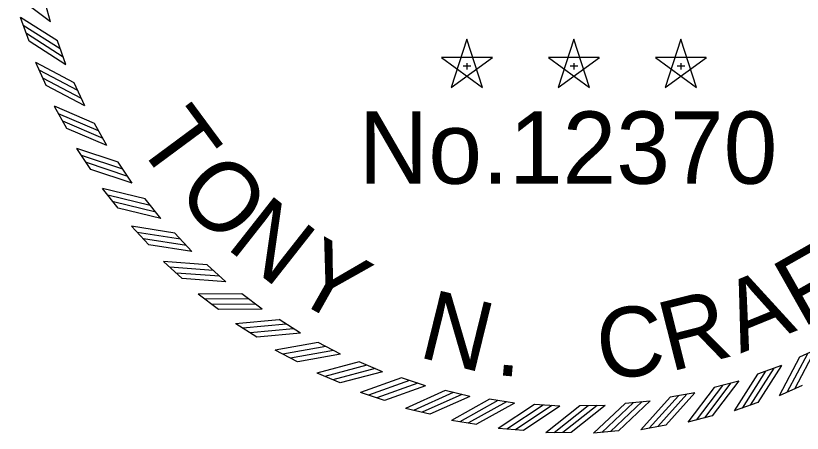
# Model space of a CAD drawing. Extents: x -712 to 3943, y 73 to 2823.
# Drawn here: x 3001.6 to 3144.5, y 203 to 278.8 of the extents above; entities that cross this region are included whole.
import ezdxf

# ---------------------------------------------------------------- set-up
doc = ezdxf.new("R2010")
doc.units = 0
doc.layers.add('STAMP_TNC', color=7, linetype='Continuous')

msp = doc.modelspace()

# ---------------------------------------------------------------- linework, layer by layer
at = {"layer": 'STAMP_TNC'}
for p, q in [((3007.88, 277.67), (3006.71, 282.11)), ((3007.88, 277.67), (3006.71, 282.11)), ((3004, 274.19), (3002.47, 278.51)), ((3004, 274.19), (3002.47, 278.51)), ((3083.56, 274.56), (3080.7, 265.76)), ((3083.56, 274.56), (3080.7, 265.76)), ((3086.42, 265.77), (3083.57, 274.57)), ((3086.42, 265.77), (3083.57, 274.57)), ((3103, 274.56), (3100.13, 265.76)), ((3103, 274.56), (3100.13, 265.76)), ((3105.86, 265.77), (3103.01, 274.57)), ((3105.86, 265.77), (3103.01, 274.57)), ((3122.43, 274.56), (3119.57, 265.76)), ((3122.43, 274.56), (3119.57, 265.76)), ((3125.29, 265.77), (3122.44, 274.57)), ((3125.29, 265.77), (3122.44, 274.57)), ((3010.68, 269.92), (3009.15, 274.25)), ((3010.68, 269.92), (3009.15, 274.25)), ((3007.1, 266.12), (3005.22, 270.3)), ((3007.1, 266.12), (3005.22, 270.3)), ((3088.19, 271.2), (3078.94, 271.21)), ((3088.19, 271.2), (3078.94, 271.21)), ((3078.94, 271.2), (3086.42, 265.75)), ((3078.94, 271.2), (3086.42, 265.75)), ((3080.71, 265.77), (3088.2, 271.2)), ((3080.71, 265.77), (3088.2, 271.2)), ((3083.57, 270.21), (3083.57, 269.05)), ((3083.57, 270.21), (3083.57, 269.05)), ((3107.62, 271.2), (3098.37, 271.21)), ((3107.62, 271.2), (3098.37, 271.21)), ((3098.38, 271.2), (3105.86, 265.75)), ((3098.38, 271.2), (3105.86, 265.75)), ((3100.14, 265.77), (3107.63, 271.2)), ((3100.14, 265.77), (3107.63, 271.2)), ((3103.01, 270.21), (3103.01, 269.05)), ((3103.01, 270.21), (3103.01, 269.05)), ((3127.06, 271.2), (3117.81, 271.21)), ((3127.06, 271.2), (3117.81, 271.21)), ((3117.81, 271.2), (3125.29, 265.75)), ((3117.81, 271.2), (3125.29, 265.75)), ((3119.58, 265.77), (3127.07, 271.2)), ((3119.58, 265.77), (3127.07, 271.2)), ((3122.44, 270.21), (3122.44, 269.05)), ((3122.44, 270.21), (3122.44, 269.05)), ((3082.91, 269.72), (3084.28, 269.72)), ((3082.91, 269.72), (3084.28, 269.72)), ((3102.34, 269.72), (3103.72, 269.72)), ((3102.34, 269.72), (3103.72, 269.72)), ((3121.78, 269.72), (3123.15, 269.72)), ((3121.78, 269.72), (3123.15, 269.72)), ((3014.11, 262.42), (3012.22, 266.61)), ((3014.11, 262.42), (3012.22, 266.61)), ((3010.85, 258.34), (3008.63, 262.35)), ((3010.85, 258.34), (3008.63, 262.35)), ((3018.14, 255.23), (3015.92, 259.25)), ((3018.14, 255.23), (3015.92, 259.25)), ((3015.23, 250.9), (3012.69, 254.71)), ((3015.23, 250.9), (3012.69, 254.71)), ((3022.76, 248.4), (3020.21, 252.23)), ((3022.76, 248.4), (3020.21, 252.23)), ((3020.21, 243.85), (3017.37, 247.44)), ((3020.21, 243.85), (3017.37, 247.44)), ((3027.92, 241.98), (3025.07, 245.58)), ((3027.92, 241.98), (3025.07, 245.58)), ((3025.76, 237.23), (3022.63, 240.57)), ((3025.76, 237.23), (3022.63, 240.57)), ((3033.6, 236), (3030.46, 239.35)), ((3033.6, 236), (3030.46, 239.35)), ((3031.84, 231.09), (3028.44, 234.16)), ((3031.84, 231.09), (3028.44, 234.16)), ((3039.75, 230.51), (3036.34, 233.59)), ((3039.75, 230.51), (3036.34, 233.59)), ((3038.4, 225.47), (3034.76, 228.25)), ((3038.4, 225.47), (3034.76, 228.25)), ((3046.33, 225.55), (3042.68, 228.34)), ((3046.33, 225.55), (3042.68, 228.34)), ((3053.3, 221.15), (3049.43, 223.63)), ((3053.3, 221.15), (3049.43, 223.63)), ((3045.41, 220.42), (3041.55, 222.89)), ((3045.41, 220.42), (3041.55, 222.89)), ((3060.61, 217.34), (3056.55, 219.49)), ((3060.61, 217.34), (3056.55, 219.49)), ((3148.2, 218.71), (3144.01, 216.83)), ((3148.2, 218.71), (3144.01, 216.83)), ((3052.8, 215.96), (3048.75, 218.1)), ((3052.8, 215.96), (3048.75, 218.1)), ((3068.21, 214.15), (3063.99, 215.96)), ((3068.21, 214.15), (3063.99, 215.96)), ((3140.7, 215.28), (3136.38, 213.75)), ((3140.7, 215.28), (3136.38, 213.75)), ((3060.54, 212.13), (3056.33, 213.93)), ((3060.54, 212.13), (3056.33, 213.93)), ((3076.05, 211.6), (3071.69, 213.05)), ((3076.05, 211.6), (3071.69, 213.05)), ((3132.95, 212.48), (3128.51, 211.32)), ((3132.95, 212.48), (3128.51, 211.32)), ((3144.5, 211.7), (3140.32, 209.82)), ((3144.5, 211.7), (3140.32, 209.82)), ((3068.57, 208.95), (3064.23, 210.39)), ((3068.57, 208.95), (3064.23, 210.39)), ((3084.07, 209.7), (3079.6, 210.78)), ((3084.07, 209.7), (3079.6, 210.78)), ((3124.99, 210.34), (3120.47, 209.54)), ((3124.99, 210.34), (3120.47, 209.54)), ((3092.22, 208.47), (3087.68, 209.18)), ((3092.22, 208.47), (3087.68, 209.18)), ((3116.89, 208.85), (3112.31, 208.43)), ((3116.89, 208.85), (3112.31, 208.43)), ((3076.84, 206.44), (3072.39, 207.52)), ((3076.84, 206.44), (3072.39, 207.52)), ((3100.44, 207.92), (3095.86, 208.25)), ((3100.44, 207.92), (3095.86, 208.25)), ((3108.68, 208.04), (3104.09, 208)), ((3108.68, 208.04), (3104.09, 208)), ((3136.44, 208.6), (3132.12, 207.07)), ((3136.44, 208.6), (3132.12, 207.07)), ((3128.14, 206.18), (3123.71, 205.01)), ((3128.14, 206.18), (3123.71, 205.01)), ((3085.28, 204.62), (3080.76, 205.34)), ((3085.28, 204.62), (3080.76, 205.34)), ((3119.68, 204.45), (3115.17, 203.65)), ((3119.68, 204.45), (3115.17, 203.65)), ((3093.85, 203.51), (3089.28, 203.85)), ((3093.85, 203.51), (3089.28, 203.85)), ((3102.48, 203.11), (3097.89, 203.07)), ((3102.48, 203.11), (3097.89, 203.07)), ((3111.11, 203.42), (3106.54, 203)), ((3111.11, 203.42), (3106.54, 203))]:
    msp.add_line(p, q, dxfattribs=at)
for points in [[(3007.89, 277.67), (3001.58, 282.47)], [(3007.89, 277.67), (3001.58, 282.47)], [(3009.15, 274.24), (3002.46, 278.51)], [(3009.15, 274.24), (3002.46, 278.51)], [(3009.64, 272.8), (3002.96, 277.06)], [(3009.64, 272.8), (3002.96, 277.06)], [(3010.2, 271.31), (3003.52, 275.58)], [(3010.2, 271.31), (3003.52, 275.58)], [(3010.68, 269.91), (3004, 274.18)], [(3010.68, 269.91), (3004, 274.18)], [(3012.22, 266.6), (3005.21, 270.3)], [(3012.22, 266.6), (3005.21, 270.3)], [(3012.84, 265.2), (3005.82, 268.91)], [(3012.84, 265.2), (3005.82, 268.91)], [(3013.52, 263.77), (3006.51, 267.47)], [(3013.52, 263.77), (3006.51, 267.47)], [(3014.11, 262.42), (3007.1, 266.12)], [(3014.11, 262.42), (3007.1, 266.12)], [(3015.92, 259.25), (3008.63, 262.36)], [(3015.92, 259.25), (3008.63, 262.36)], [(3016.65, 257.9), (3009.35, 261.01)], [(3016.65, 257.9), (3009.35, 261.01)], [(3017.45, 256.53), (3010.15, 259.64)], [(3017.45, 256.53), (3010.15, 259.64)], [(3018.15, 255.23), (3010.86, 258.34)], [(3018.15, 255.23), (3010.86, 258.34)], [(3020.21, 252.22), (3012.69, 254.72)], [(3020.21, 252.22), (3012.69, 254.72)], [(3021.05, 250.94), (3013.52, 253.44)], [(3021.05, 250.94), (3013.52, 253.44)], [(3021.96, 249.64), (3014.43, 252.13)], [(3021.96, 249.64), (3014.43, 252.13)], [(3022.76, 248.4), (3015.24, 250.9)], [(3022.76, 248.4), (3015.24, 250.9)], [(3025.07, 245.57), (3017.36, 247.44)], [(3025.07, 245.57), (3017.36, 247.44)], [(3026, 244.37), (3018.3, 246.23)], [(3026, 244.37), (3018.3, 246.23)], [(3027.02, 243.14), (3019.32, 245.01)], [(3027.02, 243.14), (3019.32, 245.01)], [(3027.93, 241.98), (3020.22, 243.85)], [(3027.93, 241.98), (3020.22, 243.85)], [(3030.46, 239.35), (3022.62, 240.57)], [(3030.46, 239.35), (3022.62, 240.57)], [(3031.49, 238.22), (3023.66, 239.45)], [(3031.49, 238.22), (3023.66, 239.45)], [(3032.61, 237.09), (3024.77, 238.31)], [(3032.61, 237.09), (3024.77, 238.31)], [(3033.6, 236), (3025.77, 237.23)], [(3033.6, 236), (3025.77, 237.23)], [(3036.34, 233.59), (3028.43, 234.16)], [(3036.34, 233.59), (3028.43, 234.16)], [(3037.47, 232.55), (3029.56, 233.13)], [(3037.47, 232.55), (3029.56, 233.13)], [(3038.67, 231.51), (3030.76, 232.09)], [(3038.67, 231.51), (3030.76, 232.09)], [(3039.75, 230.51), (3031.85, 231.09)], [(3039.75, 230.51), (3031.85, 231.09)], [(3042.68, 228.34), (3034.75, 228.25)], [(3042.68, 228.34), (3034.75, 228.25)], [(3043.89, 227.4), (3035.96, 227.32)], [(3043.89, 227.4), (3035.96, 227.32)], [(3045.17, 226.46), (3037.25, 226.38)], [(3045.17, 226.46), (3037.25, 226.38)], [(3046.34, 225.55), (3038.41, 225.47)], [(3046.34, 225.55), (3038.41, 225.47)], [(3049.44, 223.62), (3041.54, 222.89)], [(3049.44, 223.62), (3041.54, 222.89)], [(3050.71, 222.79), (3042.82, 222.05)], [(3050.71, 222.79), (3042.82, 222.05)], [(3052.07, 221.96), (3044.18, 221.23)], [(3052.07, 221.96), (3044.18, 221.23)], [(3053.31, 221.15), (3045.41, 220.42)], [(3053.31, 221.15), (3045.41, 220.42)], [(3056.55, 219.49), (3048.75, 218.1)], [(3056.55, 219.49), (3048.75, 218.1)], [(3057.9, 218.76), (3050.09, 217.38)], [(3057.9, 218.76), (3050.09, 217.38)], [(3059.32, 218.05), (3051.51, 216.66)], [(3059.32, 218.05), (3051.51, 216.66)], [(3060.62, 217.35), (3052.81, 215.96)], [(3060.62, 217.35), (3052.81, 215.96)], [(3145.42, 217.44), (3141.71, 210.43)], [(3145.42, 217.44), (3141.71, 210.43)], [(3146.85, 218.12), (3143.15, 211.11)], [(3146.85, 218.12), (3143.15, 211.11)], [(3063.99, 215.95), (3056.32, 213.93)], [(3063.99, 215.95), (3056.32, 213.93)], [(3144.02, 216.83), (3140.32, 209.82)], [(3144.02, 216.83), (3140.32, 209.82)], [(3065.39, 215.34), (3057.72, 213.31)], [(3065.39, 215.34), (3057.72, 213.31)], [(3066.87, 214.75), (3059.2, 212.72)], [(3066.87, 214.75), (3059.2, 212.72)], [(3139.31, 214.81), (3135.05, 208.13)], [(3139.31, 214.81), (3135.05, 208.13)], [(3140.71, 215.29), (3136.44, 208.61)], [(3140.71, 215.29), (3136.44, 208.61)], [(3068.22, 214.15), (3060.55, 212.13)], [(3068.22, 214.15), (3060.55, 212.13)], [(3071.69, 213.04), (3064.22, 210.39)], [(3071.69, 213.04), (3064.22, 210.39)], [(3136.38, 213.75), (3132.11, 207.07)], [(3136.38, 213.75), (3132.11, 207.07)], [(3137.82, 214.25), (3133.56, 207.56)], [(3137.82, 214.25), (3133.56, 207.56)], [(3073.14, 212.55), (3065.66, 209.9)], [(3073.14, 212.55), (3065.66, 209.9)], [(3074.66, 212.08), (3067.19, 209.43)], [(3074.66, 212.08), (3067.19, 209.43)], [(3076.05, 211.6), (3068.58, 208.95)], [(3076.05, 211.6), (3068.58, 208.95)], [(3130, 211.69), (3125.19, 205.38)], [(3130, 211.69), (3125.19, 205.38)], [(3131.53, 212.13), (3126.72, 205.82)], [(3131.53, 212.13), (3126.72, 205.82)], [(3132.96, 212.49), (3128.15, 206.18)], [(3132.96, 212.49), (3128.15, 206.18)], [(3079.61, 210.78), (3072.38, 207.52)], [(3079.61, 210.78), (3072.38, 207.52)], [(3081.09, 210.41), (3073.86, 207.15)], [(3081.09, 210.41), (3073.86, 207.15)], [(3123.54, 210.1), (3118.23, 204.21)], [(3123.54, 210.1), (3118.23, 204.21)], [(3125, 210.34), (3119.69, 204.45)], [(3125, 210.34), (3119.69, 204.45)], [(3128.52, 211.31), (3123.71, 205.01)], [(3128.52, 211.31), (3123.71, 205.01)], [(3082.64, 210.06), (3075.42, 206.8)], [(3082.64, 210.06), (3075.42, 206.8)], [(3084.07, 209.7), (3076.85, 206.44)], [(3084.07, 209.7), (3076.85, 206.44)], [(3087.69, 209.18), (3080.75, 205.33)], [(3087.69, 209.18), (3080.75, 205.33)], [(3089.19, 208.93), (3082.26, 205.08)], [(3089.19, 208.93), (3082.26, 205.08)], [(3090.77, 208.71), (3083.83, 204.87)], [(3090.77, 208.71), (3083.83, 204.87)], [(3115.42, 208.74), (3109.64, 203.31)], [(3115.42, 208.74), (3109.64, 203.31)], [(3116.89, 208.86), (3111.11, 203.43)], [(3116.89, 208.86), (3111.11, 203.43)], [(3120.48, 209.54), (3115.17, 203.65)], [(3120.48, 209.54), (3115.17, 203.65)], [(3121.98, 209.79), (3116.67, 203.9)], [(3121.98, 209.79), (3116.67, 203.9)], [(3092.22, 208.47), (3085.29, 204.63)], [(3092.22, 208.47), (3085.29, 204.63)], [(3095.87, 208.25), (3089.27, 203.85)], [(3095.87, 208.25), (3089.27, 203.85)], [(3097.39, 208.12), (3090.79, 203.72)], [(3097.39, 208.12), (3090.79, 203.72)], [(3098.98, 208.04), (3092.38, 203.64)], [(3098.98, 208.04), (3092.38, 203.64)], [(3100.45, 207.92), (3093.85, 203.52)], [(3100.45, 207.92), (3093.85, 203.52)], [(3104.1, 208), (3097.89, 203.07)], [(3104.1, 208), (3097.89, 203.07)], [(3105.62, 208), (3099.42, 203.07)], [(3105.62, 208), (3099.42, 203.07)], [(3107.21, 208.05), (3101.01, 203.12)], [(3107.21, 208.05), (3101.01, 203.12)], [(3108.69, 208.05), (3102.48, 203.12)], [(3108.69, 208.05), (3102.48, 203.12)], [(3112.32, 208.43), (3106.54, 203)], [(3112.32, 208.43), (3106.54, 203)], [(3113.84, 208.56), (3108.06, 203.13)], [(3113.84, 208.56), (3108.06, 203.13)]]:
    msp.add_lwpolyline(points, dxfattribs=at)

# ---------------------------------------------------------------- texts
for s, rotation, p in [('T', 306.5026, (3023.13, 256)), ('T', 306.5026, (3023.13, 256)), ('O', 313.7811, (3030.31, 246.29)), ('O', 313.7811, (3030.31, 246.29)), ('N', 321.7876, (3039.56, 236.77)), ('N', 321.7876, (3039.56, 236.77)), ('Y', 330.5218, (3051.05, 227.95)), ('Y', 330.5218, (3051.05, 227.95)), ('F', 29.4782, (3144.47, 222.02)), ('F', 29.4782, (3144.47, 222.02)), ('A', 22.1996, (3133.29, 217.46)), ('A', 22.1996, (3133.29, 217.46)), ('N', 346.1707, (3074.47, 216.89)), ('N', 346.1707, (3074.47, 216.89)), ('R', 14.1932, (3120.44, 214.12)), ('R', 14.1932, (3120.44, 214.12)), ('C', 6.5507, (3107.85, 212.63)), ('C', 6.5507, (3107.85, 212.63)), ('.', 354.905, (3088.57, 213.61)), ('.', 354.905, (3088.57, 213.61))]:
    msp.add_text(s, height=12.66, rotation=rotation, dxfattribs=at).set_placement(p)
msp.add_text('No.12370', height=13.119, dxfattribs=at).set_placement((3063.89, 248.3))
msp.add_text('No.12370', height=13.119, dxfattribs=at).set_placement((3063.89, 248.3))

doc.saveas('drawing.dxf')
